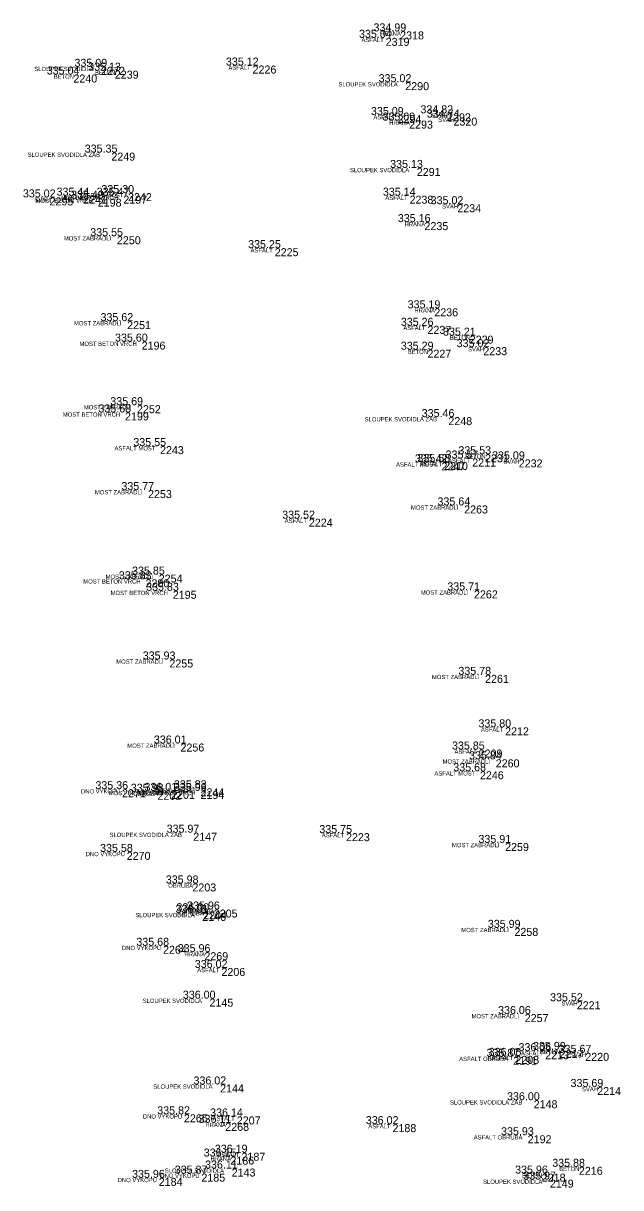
# Model space of a CAD drawing. Extents: x -597865 to -597551, y -1151663 to -1149883.
# Drawn here: x -597664.09 to -597650.08, y -1149993.59 to -1149966.3 of the extents above; entities that cross this region are included whole.
import ezdxf

# ---------------------------------------------------------------- set-up
doc = ezdxf.new("R2010")
doc.units = 0
for name, color, linetype in [('Vrstva 11', 7, 'Continuous'), ('Vrstva 12', 7, 'Continuous'), ('Vrstva 13', 7, 'Continuous'), ('Vrstva 14', 7, 'Continuous')]:
    doc.layers.add(name, color=color, linetype=linetype)

msp = doc.modelspace()

# ---------------------------------------------------------------- linework, layer by layer
at = {"layer": 'Vrstva 11'}
for p, q in [((-597655.25, -1149966.49), (-597655.25, -1149966.49)), ((-597655.59, -1149966.64), (-597655.59, -1149966.64)), ((-597662.26, -1149967.32), (-597662.26, -1149967.32)), ((-597661.94, -1149967.41), (-597661.94, -1149967.41)), ((-597658.71, -1149967.29), (-597658.71, -1149967.29)), ((-597662.91, -1149967.5), (-597662.91, -1149967.5)), ((-597655.13, -1149967.68), (-597655.13, -1149967.68)), ((-597655.31, -1149968.45), (-597655.31, -1149968.45)), ((-597654.15, -1149968.41), (-597654.15, -1149968.41)), ((-597655.04, -1149968.58), (-597655.04, -1149968.58)), ((-597654, -1149968.51), (-597654, -1149968.51)), ((-597662.02, -1149969.33), (-597662.02, -1149969.33)), ((-597654.86, -1149969.69), (-597654.86, -1149969.69)), ((-597663.47, -1149970.38), (-597663.47, -1149970.38)), ((-597662.68, -1149970.34), (-597662.68, -1149970.34)), ((-597662.34, -1149970.41), (-597662.34, -1149970.41)), ((-597661.74, -1149970.34), (-597661.74, -1149970.34)), ((-597661.63, -1149970.28), (-597661.63, -1149970.28)), ((-597655.03, -1149970.34), (-597655.03, -1149970.34)), ((-597653.91, -1149970.54), (-597653.91, -1149970.54)), ((-597654.68, -1149970.96), (-597654.68, -1149970.96)), ((-597661.89, -1149971.29), (-597661.89, -1149971.29)), ((-597658.19, -1149971.57), (-597658.19, -1149971.57)), ((-597654.45, -1149972.98), (-597654.45, -1149972.98)), ((-597661.65, -1149973.28), (-597661.65, -1149973.28)), ((-597654.61, -1149973.39), (-597654.61, -1149973.39)), ((-597653.62, -1149973.62), (-597653.62, -1149973.62)), ((-597661.31, -1149973.76), (-597661.31, -1149973.76)), ((-597654.61, -1149973.95), (-597654.61, -1149973.95)), ((-597653.3, -1149973.89), (-597653.3, -1149973.89)), ((-597661.42, -1149975.25), (-597661.42, -1149975.25)), ((-597661.7, -1149975.42), (-597661.7, -1149975.42)), ((-597654.12, -1149975.53), (-597654.12, -1149975.53)), ((-597660.88, -1149976.21), (-597660.88, -1149976.21)), ((-597653.26, -1149976.4), (-597653.26, -1149976.4)), ((-597654.28, -1149976.59), (-597654.28, -1149976.59)), ((-597654.22, -1149976.58), (-597654.22, -1149976.58)), ((-597653.56, -1149976.5), (-597653.56, -1149976.5)), ((-597652.47, -1149976.52), (-597652.47, -1149976.52)), ((-597661.16, -1149977.24), (-597661.16, -1149977.24)), ((-597653.75, -1149977.6), (-597653.75, -1149977.6)), ((-597657.39, -1149977.91), (-597657.39, -1149977.91)), ((-597661.22, -1149979.33), (-597661.22, -1149979.33)), ((-597660.91, -1149979.22), (-597660.91, -1149979.22)), ((-597660.58, -1149979.6), (-597660.58, -1149979.6)), ((-597653.52, -1149979.59), (-597653.52, -1149979.59)), ((-597660.66, -1149981.21), (-597660.66, -1149981.21)), ((-597653.26, -1149981.57), (-597653.26, -1149981.57)), ((-597652.79, -1149982.8), (-597652.79, -1149982.8)), ((-597660.4, -1149983.18), (-597660.4, -1149983.18)), ((-597653.41, -1149983.32), (-597653.41, -1149983.32)), ((-597653.01, -1149983.55), (-597653.01, -1149983.55)), ((-597653.38, -1149983.83), (-597653.38, -1149983.83)), ((-597661.77, -1149984.25), (-597661.77, -1149984.25)), ((-597660.94, -1149984.31), (-597660.94, -1149984.31)), ((-597660.62, -1149984.29), (-597660.62, -1149984.29)), ((-597659.93, -1149984.23), (-597659.93, -1149984.23)), ((-597659.93, -1149984.29), (-597659.93, -1149984.29)), ((-597660.1, -1149985.27), (-597660.1, -1149985.27)), ((-597656.52, -1149985.28), (-597656.52, -1149985.28)), ((-597652.79, -1149985.51), (-597652.79, -1149985.51)), ((-597661.66, -1149985.72), (-597661.66, -1149985.72)), ((-597660.12, -1149986.46), (-597660.12, -1149986.46)), ((-597659.89, -1149987.15), (-597659.89, -1149987.15)), ((-597659.87, -1149987.11), (-597659.87, -1149987.11)), ((-597659.62, -1149987.07), (-597659.62, -1149987.07)), ((-597652.57, -1149987.5), (-597652.57, -1149987.5)), ((-597660.81, -1149987.92), (-597660.81, -1149987.92)), ((-597659.84, -1149988.07), (-597659.84, -1149988.07)), ((-597659.44, -1149988.44), (-597659.44, -1149988.44)), ((-597659.72, -1149989.16), (-597659.72, -1149989.16)), ((-597651.11, -1149989.22), (-597651.11, -1149989.22)), ((-597652.33, -1149989.52), (-597652.33, -1149989.52)), ((-597652.6, -1149990.52), (-597652.6, -1149990.52)), ((-597652.55, -1149990.5), (-597652.55, -1149990.5)), ((-597651.85, -1149990.39), (-597651.85, -1149990.39)), ((-597651.51, -1149990.36), (-597651.51, -1149990.36)), ((-597650.91, -1149990.43), (-597650.91, -1149990.43)), ((-597659.47, -1149991.17), (-597659.47, -1149991.17)), ((-597650.63, -1149991.23), (-597650.63, -1149991.23)), ((-597652.12, -1149991.54), (-597652.12, -1149991.54)), ((-597660.32, -1149991.87), (-597660.32, -1149991.87)), ((-597659.08, -1149991.92), (-597659.08, -1149991.92)), ((-597659.35, -1149992.07), (-597659.35, -1149992.07)), ((-597655.43, -1149992.1), (-597655.43, -1149992.1)), ((-597652.26, -1149992.36), (-597652.26, -1149992.36)), ((-597658.97, -1149992.77), (-597658.97, -1149992.77)), ((-597659.23, -1149992.86), (-597659.23, -1149992.86)), ((-597659.91, -1149993.26), (-597659.91, -1149993.26)), ((-597659.2, -1149993.14), (-597659.2, -1149993.14)), ((-597651.93, -1149993.26), (-597651.93, -1149993.26)), ((-597651.06, -1149993.1), (-597651.06, -1149993.1)), ((-597660.91, -1149993.36), (-597660.91, -1149993.36)), ((-597651.74, -1149993.4), (-597651.74, -1149993.4))]:
    msp.add_line(p, q, dxfattribs=at)

# ---------------------------------------------------------------- texts
at = {"layer": 'Vrstva 12'}
for s, p in [('334.99 ', (-597655.875, -1149966.49)), ('335.04 ', (-597656.215, -1149966.64)), ('335.09 ', (-597662.885, -1149967.32)), ('335.12 ', (-597659.335, -1149967.29)), ('335.04 ', (-597663.535, -1149967.5)), ('335.13 ', (-597662.565, -1149967.41)), ('335.02 ', (-597655.755, -1149967.68)), ('334.82 ', (-597654.775, -1149968.41)), ('335.09 ', (-597655.935, -1149968.45)), ('335.09 ', (-597655.665, -1149968.58)), ('334.74 ', (-597654.625, -1149968.51)), ('335.35 ', (-597662.645, -1149969.33)), ('335.13 ', (-597655.485, -1149969.69)), ('335.30 ', (-597662.255, -1149970.28)), ('335.02 ', (-597664.095, -1149970.38)), ('335.44 ', (-597663.305, -1149970.34)), ('335.49 ', (-597662.965, -1149970.41)), ('335.47 ', (-597662.365, -1149970.34)), ('335.14 ', (-597655.655, -1149970.34)), ('335.02 ', (-597654.535, -1149970.54)), ('335.16 ', (-597655.305, -1149970.96)), ('335.55 ', (-597662.515, -1149971.29)), ('335.25 ', (-597658.815, -1149971.57)), ('335.19 ', (-597655.075, -1149972.98)), ('335.62 ', (-597662.275, -1149973.28)), ('335.26 ', (-597655.235, -1149973.39)), ('335.60 ', (-597661.935, -1149973.76)), ('335.21 ', (-597654.245, -1149973.62)), ('335.29 ', (-597655.235, -1149973.95)), ('335.02 ', (-597653.925, -1149973.89)), ('335.68 ', (-597662.325, -1149975.42)), ('335.69 ', (-597662.045, -1149975.25)), ('335.46 ', (-597654.745, -1149975.53)), ('335.55 ', (-597661.505, -1149976.21)), ('335.42 ', (-597654.905, -1149976.59)), ('335.58 ', (-597654.845, -1149976.58)), ('335.57 ', (-597654.185, -1149976.5)), ('335.53 ', (-597653.885, -1149976.4)), ('335.09 ', (-597653.095, -1149976.52)), ('335.77 ', (-597661.785, -1149977.24)), ('335.64 ', (-597654.375, -1149977.6)), ('335.52 ', (-597658.015, -1149977.91)), ('335.83 ', (-597661.845, -1149979.33)), ('335.85 ', (-597661.535, -1149979.22)), ('335.83 ', (-597661.205, -1149979.6)), ('335.71 ', (-597654.145, -1149979.59)), ('335.93 ', (-597661.285, -1149981.21)), ('335.78 ', (-597653.885, -1149981.57)), ('335.80 ', (-597653.415, -1149982.8)), ('336.01 ', (-597661.025, -1149983.18)), ('335.85 ', (-597654.035, -1149983.32)), ('335.84 ', (-597653.635, -1149983.55)), ('335.68 ', (-597654.005, -1149983.83)), ('335.36 ', (-597662.395, -1149984.25)), ('335.83 ', (-597660.555, -1149984.23)), ('335.98 ', (-597661.565, -1149984.31)), ('336.01 ', (-597661.245, -1149984.29)), ('335.96 ', (-597660.555, -1149984.29)), ('335.97 ', (-597660.725, -1149985.27)), ('335.75 ', (-597657.145, -1149985.28)), ('335.91 ', (-597653.415, -1149985.51)), ('335.58 ', (-597662.285, -1149985.72)), ('335.98 ', (-597660.745, -1149986.46)), ('336.01 ', (-597660.515, -1149987.15)), ('336.00 ', (-597660.495, -1149987.11)), ('335.96 ', (-597660.245, -1149987.07)), ('335.99 ', (-597653.195, -1149987.5)), ('335.68 ', (-597661.435, -1149987.92)), ('335.96 ', (-597660.465, -1149988.07)), ('336.02 ', (-597660.065, -1149988.44)), ('336.00 ', (-597660.345, -1149989.16)), ('335.52 ', (-597651.735, -1149989.22)), ('336.06 ', (-597652.955, -1149989.52)), ('335.87 ', (-597653.225, -1149990.52)), ('336.05 ', (-597653.175, -1149990.5)), ('336.06 ', (-597652.475, -1149990.39)), ('335.99 ', (-597652.135, -1149990.36)), ('335.67 ', (-597651.535, -1149990.43)), ('336.02 ', (-597660.095, -1149991.17)), ('335.69 ', (-597651.255, -1149991.23)), ('336.00 ', (-597652.745, -1149991.54)), ('335.82 ', (-597660.945, -1149991.87)), ('336.11 ', (-597659.975, -1149992.07)), ('336.14 ', (-597659.705, -1149991.92)), ('336.02 ', (-597656.055, -1149992.1)), ('335.93 ', (-597652.885, -1149992.36)), ('336.15 ', (-597659.855, -1149992.86)), ('336.19 ', (-597659.595, -1149992.77)), ('335.87 ', (-597660.535, -1149993.26)), ('336.11 ', (-597659.825, -1149993.14)), ('335.96 ', (-597652.555, -1149993.26)), ('335.88 ', (-597651.685, -1149993.1)), ('335.96 ', (-597661.535, -1149993.36)), ('335.97 ', (-597652.365, -1149993.4))]:
    msp.add_text(s, height=0.1875, dxfattribs=at).set_placement(p)
at = {"layer": 'Vrstva 13'}
for s, p in [('2318', (-597655.25, -1149966.677)), ('2319', (-597655.59, -1149966.828)), ('2272', (-597662.26, -1149967.508)), ('2239', (-597661.94, -1149967.597)), ('2226', (-597658.71, -1149967.478)), ('2240', (-597662.91, -1149967.688)), ('2290', (-597655.13, -1149967.867)), ('2294', (-597655.31, -1149968.637)), ('2292', (-597654.15, -1149968.597)), ('2320', (-597654, -1149968.698)), ('2293', (-597655.04, -1149968.768)), ('2249', (-597662.02, -1149969.518)), ('2291', (-597654.86, -1149969.877)), ('2295', (-597663.47, -1149970.568)), ('2241', (-597662.68, -1149970.528)), ('2198', (-597662.34, -1149970.597)), ('2197', (-597661.74, -1149970.528)), ('2242', (-597661.63, -1149970.468)), ('2238', (-597655.03, -1149970.528)), ('2234', (-597653.91, -1149970.728)), ('2235', (-597654.68, -1149971.147)), ('2250', (-597661.89, -1149971.478)), ('2225', (-597658.19, -1149971.758)), ('2236', (-597654.45, -1149973.167)), ('2251', (-597661.65, -1149973.468)), ('2237', (-597654.61, -1149973.578)), ('2229', (-597653.62, -1149973.808)), ('2196', (-597661.31, -1149973.948)), ('2227', (-597654.61, -1149974.137)), ('2233', (-597653.3, -1149974.078)), ('2252', (-597661.42, -1149975.438)), ('2199', (-597661.7, -1149975.607)), ('2248', (-597654.12, -1149975.718)), ('2243', (-597660.88, -1149976.397)), ('2231', (-597653.26, -1149976.588)), ('2247', (-597654.28, -1149976.778)), ('2210', (-597654.22, -1149976.768)), ('2211', (-597653.56, -1149976.688)), ('2232', (-597652.47, -1149976.708)), ('2253', (-597661.16, -1149977.427)), ('2263', (-597653.75, -1149977.788)), ('2224', (-597657.39, -1149978.097)), ('2200', (-597661.22, -1149979.518)), ('2254', (-597660.91, -1149979.407)), ('2195', (-597660.58, -1149979.788)), ('2262', (-597653.52, -1149979.778)), ('2255', (-597660.66, -1149981.397)), ('2261', (-597653.26, -1149981.758)), ('2212', (-597652.79, -1149982.988)), ('2256', (-597660.4, -1149983.367)), ('2209', (-597653.41, -1149983.508)), ('2260', (-597653.01, -1149983.738)), ('2246', (-597653.38, -1149984.018)), ('2271', (-597661.77, -1149984.438)), ('2202', (-597660.94, -1149984.498)), ('2201', (-597660.62, -1149984.478)), ('2244', (-597659.93, -1149984.417)), ('2194', (-597659.93, -1149984.478)), ('2147', (-597660.1, -1149985.458)), ('2223', (-597656.52, -1149985.468)), ('2259', (-597652.79, -1149985.698)), ('2270', (-597661.66, -1149985.907)), ('2203', (-597660.12, -1149986.647)), ('2146', (-597659.89, -1149987.338)), ('2204', (-597659.87, -1149987.298)), ('2205', (-597659.62, -1149987.258)), ('2258', (-597652.57, -1149987.688)), ('2264', (-597660.81, -1149988.107)), ('2269', (-597659.84, -1149988.258)), ('2206', (-597659.44, -1149988.627)), ('2145', (-597659.72, -1149989.347)), ('2221', (-597651.11, -1149989.407)), ('2257', (-597652.33, -1149989.708)), ('2191', (-597652.6, -1149990.708)), ('2208', (-597652.55, -1149990.688)), ('2213', (-597651.85, -1149990.578)), ('2217', (-597651.51, -1149990.548)), ('2220', (-597650.91, -1149990.617)), ('2144', (-597659.47, -1149991.357)), ('2214', (-597650.63, -1149991.417)), ('2148', (-597652.12, -1149991.728)), ('2265', (-597660.32, -1149992.058)), ('2207', (-597659.08, -1149992.107)), ('2268', (-597659.35, -1149992.258)), ('2188', (-597655.43, -1149992.288)), ('2192', (-597652.26, -1149992.548)), ('2187', (-597658.97, -1149992.958)), ('2186', (-597659.23, -1149993.048)), ('2185', (-597659.91, -1149993.448)), ('2143', (-597659.2, -1149993.328)), ('2218', (-597651.93, -1149993.448)), ('2216', (-597651.06, -1149993.288)), ('2184', (-597660.91, -1149993.548)), ('2149', (-597651.74, -1149993.588))]:
    msp.add_text(s, height=0.1875, dxfattribs=at).set_placement(p)
at = {"layer": 'Vrstva 14'}
for s, p in [('HRANA', (-597655.717, -1149966.59)), ('ASFALT', (-597656.157, -1149966.74)), ('SLOUPEK SVODIDLA', (-597663.827, -1149967.42)), ('BETON', (-597662.403, -1149967.51)), ('ASFALT', (-597659.277, -1149967.39)), ('BETON', (-597663.373, -1149967.6)), ('SLOUPEK SVODIDLA', (-597656.697, -1149967.78)), ('ASFALT', (-597655.877, -1149968.55)), ('SVAH', (-597654.508, -1149968.51)), ('SVAH', (-597654.358, -1149968.61)), ('HRANA', (-597655.507, -1149968.68)), ('SLOUPEK SVODIDLA ZAB', (-597663.983, -1149969.43)), ('SLOUPEK SVODIDLA', (-597656.427, -1149969.79)), ('SVAH', (-597663.828, -1149970.48)), ('MOST BETON VRCH', (-597663.798, -1149970.51)), ('MOST BETON VRCH', (-597663.198, -1149970.44)), ('BETON', (-597663.143, -1149970.44)), ('ASFALT MOST', (-597662.697, -1149970.38)), ('ASFALT', (-597655.597, -1149970.44)), ('SVAH', (-597654.268, -1149970.64)), ('HRANA', (-597655.147, -1149971.06)), ('MOST ZABRADLI', (-597663.136, -1149971.39)), ('ASFALT', (-597658.757, -1149971.67)), ('HRANA', (-597654.917, -1149973.08)), ('MOST ZABRADLI', (-597662.896, -1149973.38)), ('ASFALT', (-597655.177, -1149973.49)), ('BETON', (-597654.083, -1149973.72)), ('MOST BETON VRCH', (-597662.768, -1149973.86)), ('BETON', (-597655.073, -1149974.05)), ('SVAH', (-597653.658, -1149973.99)), ('MOST ZABRADLI', (-597662.666, -1149975.35)), ('MOST BETON VRCH', (-597663.158, -1149975.52)), ('SLOUPEK SVODIDLA ZAB', (-597656.083, -1149975.63)), ('ASFALT MOST', (-597661.947, -1149976.31)), ('BETON', (-597653.723, -1149976.5)), ('ASFALT MOST', (-597655.347, -1149976.69)), ('ASFALT', (-597654.787, -1149976.68)), ('ASFALT', (-597654.127, -1149976.6)), ('SVAH', (-597652.828, -1149976.62)), ('MOST ZABRADLI', (-597662.406, -1149977.34)), ('MOST ZABRADLI', (-597654.996, -1149977.7)), ('ASFALT', (-597657.957, -1149978.01)), ('MOST BETON VRCH', (-597662.678, -1149979.43)), ('MOST ZABRADLI', (-597662.156, -1149979.32)), ('MOST BETON VRCH', (-597662.038, -1149979.7)), ('MOST ZABRADLI', (-597654.766, -1149979.69)), ('MOST ZABRADLI', (-597661.906, -1149981.31)), ('MOST ZABRADLI', (-597654.506, -1149981.67)), ('ASFALT', (-597653.357, -1149982.9)), ('MOST ZABRADLI', (-597661.646, -1149983.28)), ('ASFALT', (-597653.977, -1149983.42)), ('MOST ZABRADLI', (-597654.256, -1149983.65)), ('ASFALT MOST', (-597654.447, -1149983.93)), ('DNO VYKOPU', (-597662.733, -1149984.35)), ('MOST BETON VRCH', (-597662.078, -1149984.39)), ('OBRUBA', (-597661.507, -1149984.41)), ('MOST BETON VRCH', (-597661.388, -1149984.39)), ('ASFALT MOST', (-597660.997, -1149984.33)), ('SLOUPEK SVODIDLA ZAB', (-597662.063, -1149985.37)), ('ASFALT', (-597657.087, -1149985.38)), ('MOST ZABRADLI', (-597654.036, -1149985.61)), ('DNO VYKOPU', (-597662.623, -1149985.82)), ('OBRUBA', (-597660.687, -1149986.56)), ('SLOUPEK SVODIDLA', (-597661.457, -1149987.25)), ('OBRUBA', (-597660.437, -1149987.21)), ('OBRUBA', (-597660.187, -1149987.17)), ('MOST ZABRADLI', (-597653.816, -1149987.6)), ('DNO VYKOPU', (-597661.772, -1149988.02)), ('HRANA', (-597660.307, -1149988.17)), ('ASFALT', (-597660.007, -1149988.54)), ('SLOUPEK SVODIDLA', (-597661.287, -1149989.26)), ('SVAH', (-597651.468, -1149989.32)), ('MOST ZABRADLI', (-597653.576, -1149989.62)), ('ASFALT OBRUBA', (-597653.867, -1149990.62)), ('ASFALT', (-597653.117, -1149990.6)), ('ASFALT', (-597652.417, -1149990.49)), ('BETON', (-597651.973, -1149990.46)), ('SVAH', (-597651.268, -1149990.53)), ('SLOUPEK SVODIDLA', (-597661.037, -1149991.27)), ('SVAH', (-597650.988, -1149991.33)), ('SLOUPEK SVODIDLA ZAB', (-597654.083, -1149991.64)), ('DNO VYKOPU', (-597661.282, -1149991.97)), ('ASFALT', (-597659.647, -1149992.02)), ('HRANA', (-597659.817, -1149992.17)), ('ASFALT', (-597655.997, -1149992.2)), ('ASFALT OBRUBA', (-597653.527, -1149992.46)), ('ASFALT', (-597659.537, -1149992.87)), ('HRANA', (-597659.697, -1149992.96)), ('DNO VYKOPU', (-597660.873, -1149993.36)), ('SLOUPEK SVODIDLA', (-597660.767, -1149993.24)), ('BETON', (-597652.393, -1149993.36)), ('BETON', (-597651.523, -1149993.2)), ('DNO VYKOPU', (-597661.873, -1149993.46)), ('SLOUPEK SVODIDLA', (-597653.307, -1149993.5))]:
    msp.add_text(s, height=0.1, dxfattribs=at).set_placement(p)

doc.saveas('drawing.dxf')
